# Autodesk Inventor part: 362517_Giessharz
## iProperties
Company: Mayer & Müller AG Schaltgeräte
Created: 2006-10
Material: PU123 / PU88
Document SubType Name: Modeling
Designer: I.Baliuc
Manufacturer: Standard
Standards Organization: Custom
Description: Gießharz / Härter
Density: 0.94 g/cm^3
Author: T.Messerschmitt
Keywords: 384055 / 384085
Revision Number: 384055 / 384085
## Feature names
1. Extrusion2
2. Extrusion3
3. Extrusion4
4. Extrusion5
